(* Logix 5000 project; controller A1000_Sample vendor 1 type 14 code 87 rev 20.19; software revision 20.05 *)

TASK MainTask (continuous, watchdog 500 ms) : MainProgram

MODULES
   Controller : vendor 1 type 14 code 87 (CompactLogixL23E_QB1_Controller 0, rev 20.19)
      LocalENB : vendor 1 type 12 code 190 (CompactLogixL23E_QB1_Ethernet 1, rev 20.11)
         A1000D : vendor 678 type 780 code 3073 (Ethernet 192.168.1.218, rev 1.1, StandardDataDriven RPI 60 ms)   // A1000 Dimensioner Device
      Local : CompactBus (CompactVirtualAdapter 3, rev 20.11)
         Discrete_Inputs : vendor 1 type 7 code 320 (Compact 1, rev 3.1, Input RPI 20 ms)
         Discrete_Outputs : vendor 1 type 7 code 322 (Compact 2, rev 3.1, Output RPI 20 ms)
END_MODULES

TYPE A1000D_CONTROL :
STRUCT
   TriggerEnable : BOOL;
   BufferResultsEnable : BOOL;
   reserved_0_2 : BOOL;
   reserved_0_3 : BOOL;
   ExecuteCommand : BOOL;
   reserved_0_5 : BOOL;
   ClearError : BOOL;
   reserved_0_7 : BOOL;
   CommandID : INT;
   SoftEvent0 : BOOL;
   SoftEvent1 : BOOL;
   SoftEvent2 : BOOL;
   SoftEvent3 : BOOL;
   SoftEvent4 : BOOL;
   SoftEvent5 : BOOL;
   SoftEvent6 : BOOL;
   SoftEvent7 : BOOL;
   SoftEvent8 : BOOL;
   SoftEvent9 : BOOL;
   SoftEvent10 : BOOL;
   SoftEvent11 : BOOL;
   SoftEvent12 : BOOL;
   SoftEvent13 : BOOL;
   SoftEvent14 : BOOL;
   SoftEvent15 : BOOL;
   SoftEvent16 : BOOL;
   SoftEvent17 : BOOL;
   SoftEvent18 : BOOL;
   SoftEvent19 : BOOL;
   SoftEvent20 : BOOL;
   SoftEvent21 : BOOL;
   SoftEvent22 : BOOL;
   SoftEvent23 : BOOL;
   SoftEvent24 : BOOL;
   SoftEvent25 : BOOL;
   SoftEvent26 : BOOL;
   SoftEvent27 : BOOL;
   SoftEvent28 : BOOL;
   SoftEvent29 : BOOL;
   SoftEvent30 : BOOL;
   SoftEvent31 : BOOL;
   TriggerCamera0 : BOOL;
   InspectionResultsAck0 : BOOL;
   ClearExposureComplete0 : BOOL;
   SetUserData0 : BOOL;
   reserved_16_4 : BOOL;
   reserved_16_5 : BOOL;
   reserved_16_6 : BOOL;
   reserved_16_7 : BOOL;
   TriggerCamera1 : BOOL;
   InspectionResultsAck1 : BOOL;
   ClearExposureComplete1 : BOOL;
   SetUserData1 : BOOL;
   reserved_17_4 : BOOL;
   reserved_17_5 : BOOL;
   reserved_17_6 : BOOL;
   reserved_17_7 : BOOL;
   TriggerCamera2 : BOOL;
   InspectionResultsAck2 : BOOL;
   ClearExposureComplete2 : BOOL;
   SetUserData2 : BOOL;
   reserved_18_4 : BOOL;
   reserved_18_5 : BOOL;
   reserved_18_6 : BOOL;
   reserved_18_7 : BOOL;
   TriggerCamera3 : BOOL;
   InspectionResultsAck3 : BOOL;
   ClearExposureComplete3 : BOOL;
   SetUserData3 : BOOL;
   reserved_19_4 : BOOL;
   reserved_19_5 : BOOL;
   reserved_19_6 : BOOL;
   reserved_19_7 : BOOL;
END_STRUCT
END_TYPE

TYPE A1000D_IN :
STRUCT
   Status : A1000D_STATUS;
   InspectionResults : SINT[452];
END_STRUCT
END_TYPE

TYPE A1000D_OUT :
STRUCT
   Control : A1000D_CONTROL;
   UserData : SINT[480];
END_STRUCT
END_TYPE

TYPE A1000D_STATUS :
STRUCT
   SystemReady : BOOL;
   reserved_0_1 : BOOL;
   reserved_0_2 : BOOL;
   reserved_0_3 : BOOL;
   reserved_0_4 : BOOL;
   reserved_0_5 : BOOL;
   ProcessingEnabled : BOOL;
   RunMode : BOOL;
   reserved_1_0 : BOOL;
   reserved_1_1 : BOOL;
   reserved_1_2 : BOOL;
   reserved_1_3 : BOOL;
   CommandExecuting : BOOL;
   CommandCompleted : BOOL;
   CommandFailed : BOOL;
   Error : BOOL;
   CommandResultCode : INT;
   ErrorID : INT;
   SoftEventAck0 : BOOL;
   SoftEventAck1 : BOOL;
   SoftEventAck2 : BOOL;
   SoftEventAck3 : BOOL;
   SoftEventAck4 : BOOL;
   SoftEventAck5 : BOOL;
   SoftEventAck6 : BOOL;
   SoftEventAck7 : BOOL;
   SoftEventAck8 : BOOL;
   SoftEventAck9 : BOOL;
   SoftEventAck10 : BOOL;
   SoftEventAck11 : BOOL;
   SoftEventAck12 : BOOL;
   SoftEventAck13 : BOOL;
   SoftEventAck14 : BOOL;
   SoftEventAck15 : BOOL;
   SoftEventAck16 : BOOL;
   SoftEventAck17 : BOOL;
   SoftEventAck18 : BOOL;
   SoftEventAck19 : BOOL;
   SoftEventAck20 : BOOL;
   SoftEventAck21 : BOOL;
   SoftEventAck22 : BOOL;
   SoftEventAck23 : BOOL;
   SoftEventAck24 : BOOL;
   SoftEventAck25 : BOOL;
   SoftEventAck26 : BOOL;
   SoftEventAck27 : BOOL;
   SoftEventAck28 : BOOL;
   SoftEventAck29 : BOOL;
   SoftEventAck30 : BOOL;
   SoftEventAck31 : BOOL;
   TriggerReady0 : BOOL;
   TriggerAck0 : BOOL;
   AcqError0 : BOOL;
   ExposureCompleted0 : BOOL;
   InspectionCompleted0 : BOOL;
   ResultsValid0 : BOOL;
   InspectionPassed0 : BOOL;
   ResultsBufferOverrun0 : BOOL;
   SetUserDataAck0 : BOOL;
   reserved_17_1 : BOOL;
   reserved_17_2 : BOOL;
   reserved_17_3 : BOOL;
   reserved_17_4 : BOOL;
   reserved_17_5 : BOOL;
   reserved_17_6 : BOOL;
   reserved_17_7 : BOOL;
   AcquiredImageID0 : INT;
   InspectedImageID0 : INT;
   InspectionResultCode0 : INT;
   TriggerReady1 : BOOL;
   TriggerAck1 : BOOL;
   AcqError1 : BOOL;
   ExposureCompleted1 : BOOL;
   InspectionCompleted1 : BOOL;
   ResultsValid1 : BOOL;
   InspectionPassed1 : BOOL;
   ResultsBufferOverrun1 : BOOL;
   SetUserDataAck1 : BOOL;
   reserved_25_1 : BOOL;
   reserved_25_2 : BOOL;
   reserved_25_3 : BOOL;
   reserved_25_4 : BOOL;
   reserved_25_5 : BOOL;
   reserved_25_6 : BOOL;
   reserved_25_7 : BOOL;
   TriggerReady2 : BOOL;
   TriggerAck2 : BOOL;
   AcqError2 : BOOL;
   ExposureCompleted2 : BOOL;
   InspectionCompleted2 : BOOL;
   ResultsValid2 : BOOL;
   InspectionPassed2 : BOOL;
   ResultsBufferOverrun2 : BOOL;
   SetUserDataAck2 : BOOL;
   reserved_33_1 : BOOL;
   reserved_33_2 : BOOL;
   reserved_33_3 : BOOL;
   reserved_33_4 : BOOL;
   reserved_33_5 : BOOL;
   reserved_33_6 : BOOL;
   reserved_33_7 : BOOL;
   TriggerReady3 : BOOL;
   TriggerAck3 : BOOL;
   AcqError3 : BOOL;
   ExposureCompleted3 : BOOL;
   InspectionCompleted3 : BOOL;
   ResultsValid3 : BOOL;
   InspectionPassed3 : BOOL;
   ResultsBufferOverrun3 : BOOL;
   SetUserDataAck3 : BOOL;
   reserved_41_1 : BOOL;
   reserved_41_2 : BOOL;
   reserved_41_3 : BOOL;
   reserved_41_4 : BOOL;
   reserved_41_5 : BOOL;
   reserved_41_6 : BOOL;
   reserved_41_7 : BOOL;
END_STRUCT
END_TYPE

VAR_GLOBAL   (* controller tags *)
   carrier_id_cnt : COUNTER;   // Generates a carrier ID number to be sent to the A1000 Item Detect Device
END_VAR

PROGRAM MainProgram   (* main routine MainRoutine *)
VAR
   A1000D_in : A1000D_IN;
   A1000D_out : A1000D_OUT;
   Carrier_ID : DINT := 1271;
   Carrier_Occupied : SINT := 1;
   clear_statistics : SINT;   // Bit 0 of clear_statistics tells the A1000 Item Detect device to clear the statistics the next time the device is triggered.
   Height : REAL := 205.03847;
   Induct_Status : DINT;
   inspectionComplete : BOOL;
   Item_Spanning : SINT;
   Length : REAL := 374.35336;
   Multi_Item_Count : DINT := 2;
   Mutli_Item_Flag : SINT;
   oneshots : BOOL[32] := ([1] := 1);
        [0]   // if insp complete goes true
        [1]   // if insp complete goes false
   Overhang_Item_Status : DINT;
   Positional_String_Data : STRING;
   Result_String_Data : STRING;
   Rotation_Deg : REAL := -3.7751946;
   Rotation_Rad : REAL := -0.06588958;
   Status_Bits : DINT := 1;
   tmrInspCompleteOut : TIMER := (PRE := 50);
   tmrTriggerFrequency : TIMER := (PRE := 750);   // Period of time between triggers when auto timed is enabled.
   tmrTriggerOn : TIMER := (PRE := 50);   // Duration bit will be held high for.
   Total_Empty : DINT;
   Total_Occupied : DINT := 20;
   Total_Triggers : DINT := 20;
   train_status : SINT;
   Tray_Alignment_X : REAL := -0.108286925;
   Tray_Alignment_Y : REAL := 0.559212;
   Tray_Alignment_Z : REAL := -0.08206848;
   Tray_Rotation_X : REAL := 0.07226294;
   Tray_Rotation_Y : REAL := -0.012458674;
   Tray_Rotation_Z : REAL := 0.07226294;
   Trigger_ID : DINT := 20;
   triggerAutoTimed : BOOL;   // Enables timed triggering
   triggerAutoTimed1 : BOOL;   // Enables timed triggering
   triggerCamera : BOOL;   // Set high if manual or auto timed triggering is enabled.
   triggerManualSingle : BOOL;   // Enables single trigger execution. One exection per toggle on.
   Width : REAL := 354.39505;
   Zones_Occupied : SINT := 3;
END_VAR

ROUTINE MainRoutine   (* ladder *)
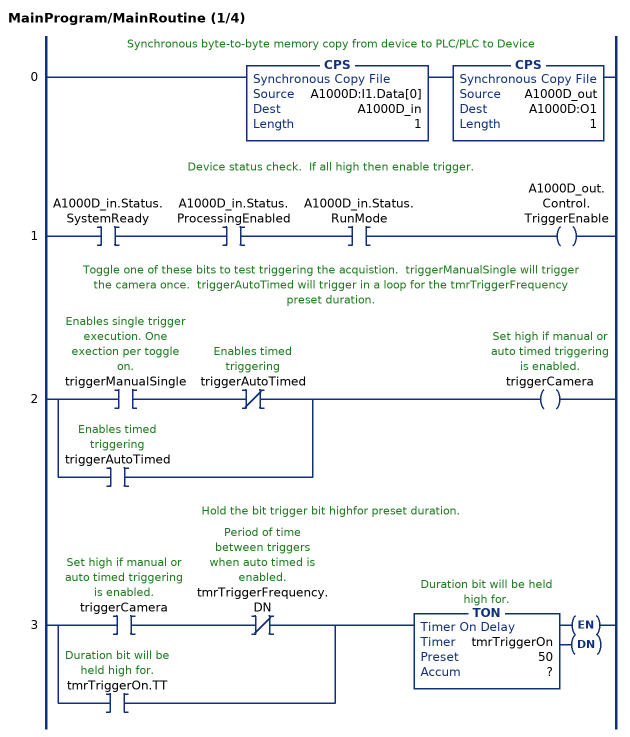
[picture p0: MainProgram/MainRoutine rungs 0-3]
   // Synchronous byte-to-byte memory copy from device to PLC/PLC to Device
   0: CPS(A1000D:I1.Data[0],A1000D_in,1)CPS(A1000D_out,A1000D:O1,1);
   // Device status check.  If all high then enable trigger.
   1: XIC(A1000D_in.Status.SystemReady)XIC(A1000D_in.Status.ProcessingEnabled)XIC(A1000D_in.Status.RunMode)OTE(A1000D_out.Control.TriggerEnable);
   // Toggle one of these bits to test triggering the acquistion.  triggerManualSingle will trigger the camera once.  triggerAutoTimed will trigger in a loop for the tmrTriggerFrequency preset duration.
   2: [XIC(triggerManualSingle) XIO(triggerAutoTimed) ,XIC(triggerAutoTimed) ]OTE(triggerCamera);
   // Hold the bit trigger bit highfor preset duration.
   3: [XIC(triggerCamera) XIO(tmrTriggerFrequency.DN) ,XIC(tmrTriggerOn.TT) ]TON(tmrTriggerOn,?,?);
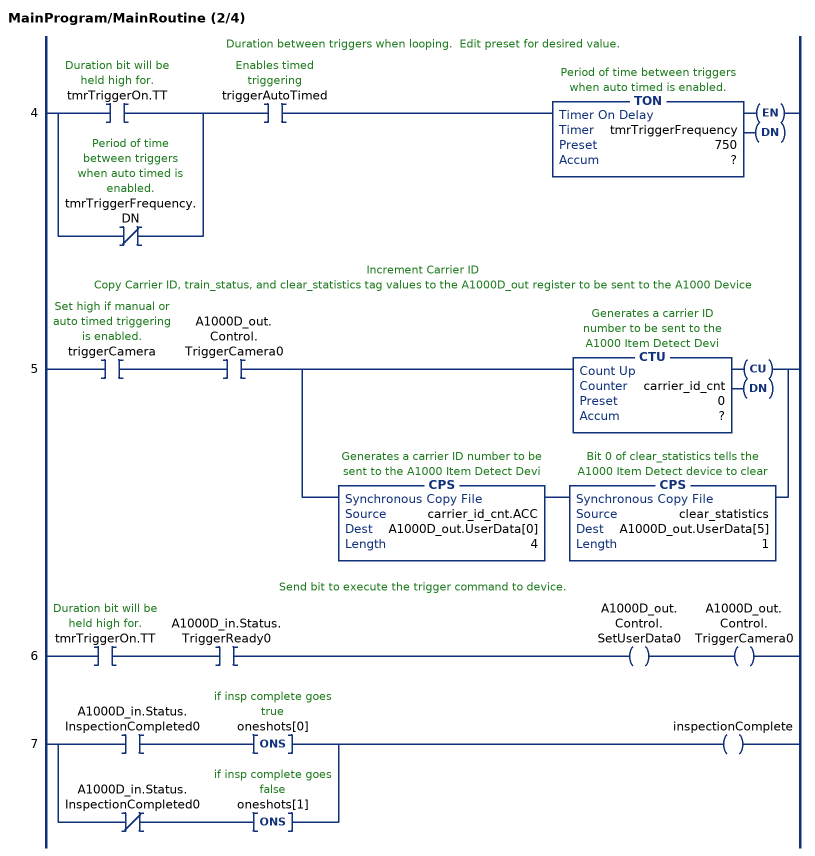
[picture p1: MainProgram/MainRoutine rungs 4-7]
   // Duration between triggers when looping.  Edit preset for desired value.
   4: [XIC(tmrTriggerOn.TT) ,XIO(tmrTriggerFrequency.DN) ]XIC(triggerAutoTimed)TON(tmrTriggerFrequency,?,?);
   // Increment Carrier ID
   // Copy Carrier ID, train_status, and clear_statistics tag values to the A1000D_out register to be sent to the A1000 Device
   5: XIC(triggerCamera)XIC(A1000D_out.Control.TriggerCamera0)[CTU(carrier_id_cnt,?,?) ,CPS(carrier_id_cnt.ACC,A1000D_out.UserData[0],4) CPS(clear_statistics,A1000D_out.UserData[5],1) ];
   // Send bit to execute the trigger command to device.
   6: XIC(tmrTriggerOn.TT)XIC(A1000D_in.Status.TriggerReady0)OTE(A1000D_out.Control.SetUserData0)OTE(A1000D_out.Control.TriggerCamera0);
   7: [XIC(A1000D_in.Status.InspectionCompleted0) ONS(oneshots[0]) ,XIO(A1000D_in.Status.InspectionCompleted0) ONS(oneshots[1]) ]OTE(inspectionComplete);
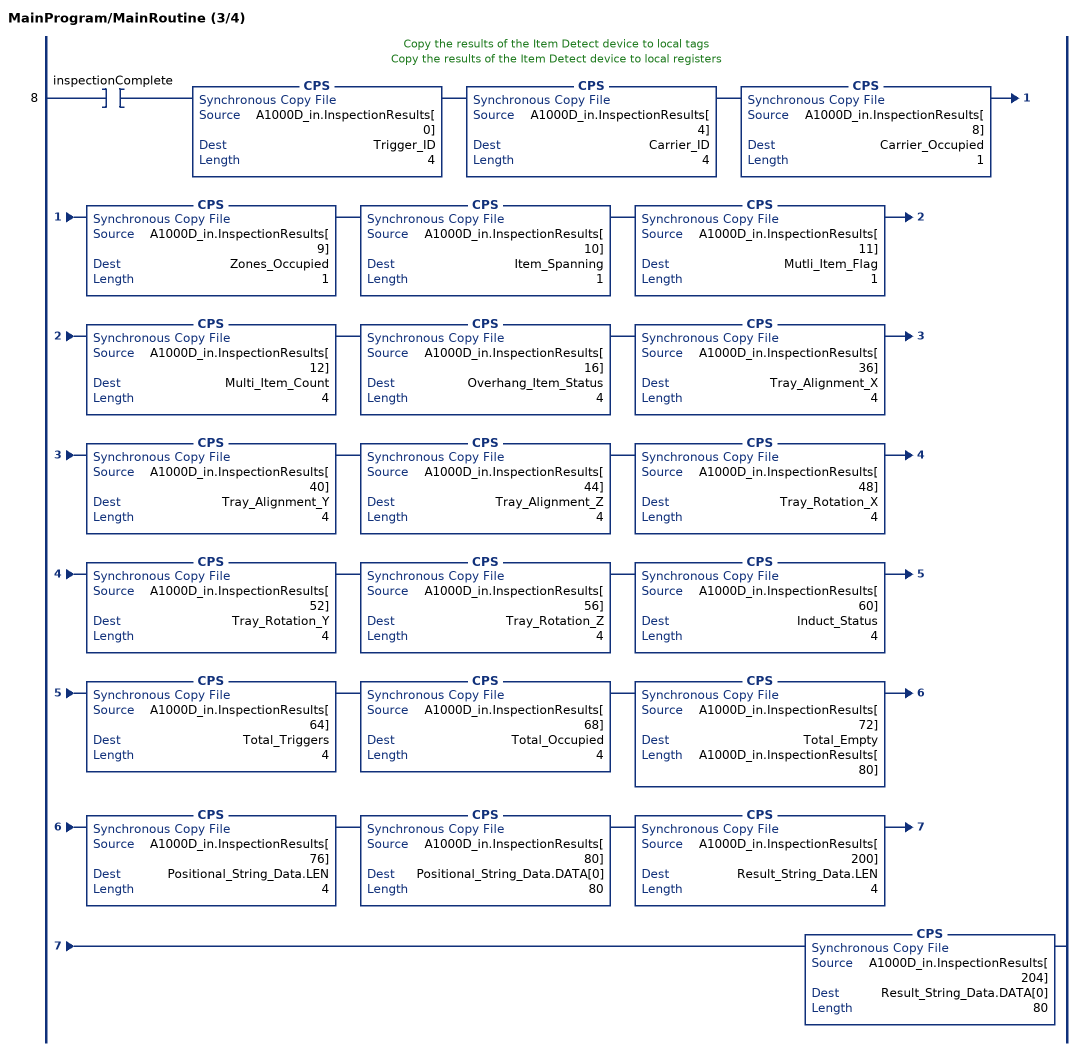
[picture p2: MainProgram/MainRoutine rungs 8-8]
   // Copy the results of the Item Detect device to local tags
   // Copy the results of the Item Detect device to local registers
   8: XIC(inspectionComplete)CPS(A1000D_in.InspectionResults[0],Trigger_ID,4)CPS(A1000D_in.InspectionResults[4],Carrier_ID,4)CPS(A1000D_in.InspectionResults[8],Carrier_Occupied,1)CPS(A1000D_in.InspectionResults[9],Zones_Occupied,1)CPS(A1000D_in.InspectionResults[10],Item_Spanning,1)CPS(A1000D_in.InspectionResults[11],Mutli_Item_Flag,1)CPS(A1000D_in.InspectionResults[12],Multi_Item_Count,4)CPS(A1000D_in.InspectionResults[16],Overhang_Item_Status,4)CPS(A1000D_in.InspectionResults[36],Tray_Alignment_X,4)CPS(A1000D_in.InspectionResults[40],Tray_Alignment_Y,4)CPS(A1000D_in.InspectionResults[44],Tray_Alignment_Z,4)CPS(A1000D_in.InspectionResults[48],Tray_Rotation_X,4)CPS(A1000D_in.InspectionResults[52],Tray_Rotation_Y,4)CPS(A1000D_in.InspectionResults[56],Tray_Rotation_Z,4)CPS(A1000D_in.InspectionResults[60],Induct_Status,4)CPS(A1000D_in.InspectionResults[64],Total_Triggers,4)CPS(A1000D_in.InspectionResults[68],Total_Occupied,4)CPS(A1000D_in.InspectionResults[72],Total_Empty,A1000D_in.InspectionResults[80])CPS(A1000D_in.InspectionResults[76],Positional_String_Data.LEN,4)CPS(A1000D_in.InspectionResults[80],Positional_String_Data.DATA[0],80)CPS(A1000D_in.InspectionResults[200],Result_String_Data.LEN,4)CPS(A1000D_in.InspectionResults[204],Result_String_Data.DATA[0],80);
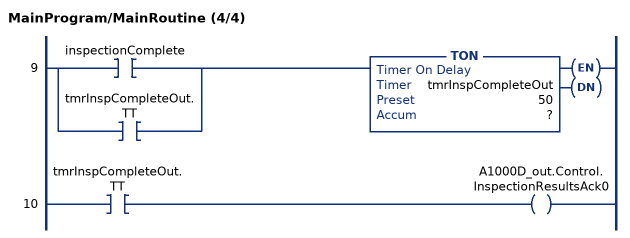
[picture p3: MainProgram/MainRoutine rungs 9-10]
   9: [XIC(inspectionComplete) ,XIC(tmrInspCompleteOut.TT) ]TON(tmrInspCompleteOut,?,?);
   10: XIC(tmrInspCompleteOut.TT)OTE(A1000D_out.Control.InspectionResultsAck0);
END_ROUTINE
END_PROGRAM
